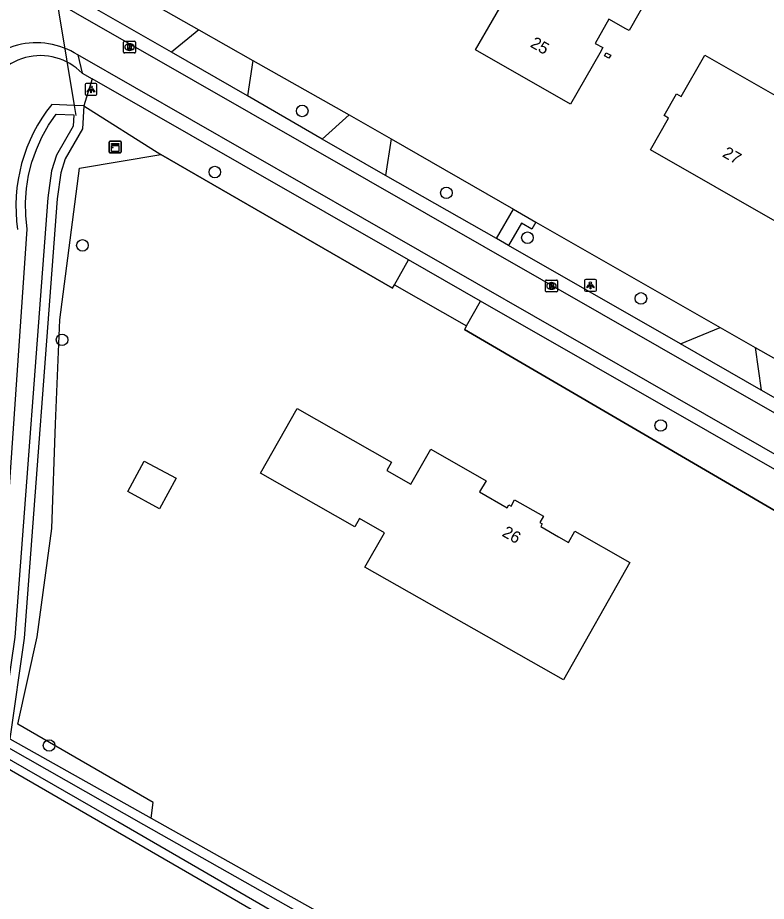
# Model space of a CAD drawing. Extents: x 156502 to 159074, y 384229 to 386094.
# Drawn here: x 157042.4 to 157105.6, y 385709.8 to 385784.4 of the extents above; entities that cross this region are included whole.
import ezdxf

# ---------------------------------------------------------------- set-up
doc = ezdxf.new("R2010")
doc.units = 0
for name, color, linetype in [('IMGEO_Berm_groen', 7, 'Continuous'), ('IMGEO_Berm_halfverhard', 7, 'Continuous'), ('IMGEO_Boom', 7, 'Continuous'), ('IMGEO_Duiker', 7, 'Continuous'), ('IMGEO_Erf', 7, 'Continuous'), ('IMGEO_Grasland_agrarisch', 7, 'Continuous'), ('IMGEO_Groenvoorziening', 7, 'Continuous'), ('IMGEO_Hek', 7, 'Continuous'), ('IMGEO_Kast', 7, 'Continuous'), ('IMGEO_Lichtpunt', 7, 'Continuous'), ('IMGEO_Muur', 7, 'Continuous'), ('IMGEO_Pand', 7, 'Continuous'), ('IMGEO_Pand_nummerreeks', 7, 'Continuous'), ('IMGEO_Rijbaan_lokaal_gesloten', 7, 'Continuous'), ('IMGEO_Rijbaan_lokaal_halfverhard', 7, 'Continuous'), ('IMGEO_Rijbaan_lokaal_open', 7, 'Continuous'), ('IMGEO_Rioolput', 7, 'Continuous'), ('IMGEO_Voetpad_open', 7, 'Continuous'), ('IMGEO_Waterloop', 7, 'Continuous')]:
    doc.layers.add(name, color=color, linetype=linetype)

msp = doc.modelspace()

# ---------------------------------------------------------------- linework, layer by layer
at = {"layer": 'IMGEO_Berm_groen'}
for points in [[(157062.278, 385780.824), (157070.393, 385776.216)], [(157073.942, 385774.201), (157084.266, 385768.252)], [(157086.152, 385767.162), (157101.744, 385758.276)], [(157104.7, 385756.591), (157109.515, 385753.847), (157111.678, 385752.607)]]:
    msp.add_lwpolyline(points, dxfattribs=at)
at = {"layer": 'IMGEO_Berm_halfverhard'}
msp.add_arc((157044.326, 385776.302), 4.923, 44.34925, 165.54113, dxfattribs=at)
at = {"layer": 'IMGEO_Boom'}
for centre in [(157066.435, 385776.556), (157059.057, 385771.395), (157078.606, 385769.643), (157085.455, 385765.849), (157047.874, 385765.203), (157095.045, 385760.722), (157046.154, 385757.226), (157096.713, 385749.995), (157045.059, 385722.974)]:
    msp.add_circle(centre, 0.489, dxfattribs=at)
at = {"layer": 'IMGEO_Duiker'}
msp.add_lwpolyline([(157047.357, 385776.176), (157047.216, 385777.024), (157043.935, 385796.78)], dxfattribs=at)
at = {"layer": 'IMGEO_Erf'}
msp.add_lwpolyline([(157053.67, 385716.85), (157130.083, 385674.016), (157162.143, 385703.286), (157165.17, 385704.25)], dxfattribs=at)
at = {"layer": 'IMGEO_Grasland_agrarisch'}
msp.add_lwpolyline([(157041.361, 385721.169), (157128.6, 385670.699)], dxfattribs=at)
at = {"layer": 'IMGEO_Groenvoorziening'}
for points in [[(157048.314, 385802.061), (157048.565, 385801.621), (157048.579, 385793.832), (157048.701, 385788.533), (157057.714, 385783.415)], [(157048.686, 385779.263), (157047.987, 385776.991)], [(157047.987, 385776.991), (157047.892, 385775.032), (157046.412, 385772.497), (157046.044, 385771.329), (157045.742, 385769.133), (157042.959, 385732.042), (157041.74, 385723.537)], [(157047.987, 385776.991), (157047.216, 385777.024), (157045.283, 385777.106)], [(157047.987, 385776.991), (157054.491, 385772.88)], [(157053.67, 385716.85), (157053.851, 385718.152), (157042.415, 385724.776), (157044.054, 385732.143), (157045.294, 385741.29), (157045.604, 385750.127), (157045.953, 385758.926), (157047.62, 385771.736), (157054.491, 385772.88)], [(157054.491, 385772.88), (157074.046, 385761.597), (157074.239, 385761.861)], [(157080.304, 385758.402), (157080.131, 385758.103), (157108.063, 385741.81), (157108.687, 385738.705)], [(157041.74, 385723.537), (157053.67, 385716.85)]]:
    msp.add_lwpolyline(points, dxfattribs=at)
msp.add_arc((157055.983, 385768.504), 13.729, 141.20338, 188.18721, dxfattribs=at)
at = {"layer": 'IMGEO_Hek'}
for points in [[(157048.314, 385802.061), (157048.565, 385801.621), (157048.579, 385793.832), (157048.701, 385788.533), (157057.714, 385783.415)], [(157057.714, 385783.415), (157062.278, 385780.824)], [(157062.278, 385780.824), (157070.393, 385776.216)], [(157070.393, 385776.216), (157073.942, 385774.201)], [(157073.942, 385774.201), (157084.266, 385768.252)], [(157074.046, 385761.597), (157054.491, 385772.88)], [(157084.266, 385768.252), (157086.152, 385767.162)], [(157086.152, 385767.162), (157101.744, 385758.276)], [(157108.687, 385738.705), (157108.063, 385741.81), (157080.131, 385758.103)], [(157101.744, 385758.276), (157104.7, 385756.591)], [(157104.7, 385756.591), (157109.515, 385753.847)]]:
    msp.add_lwpolyline(points, dxfattribs=at)
at = {"layer": 'IMGEO_Kast'}
for p, q in [((157050.14, 385773.083), (157050.14, 385773.924)), ((157050.14, 385773.924), (157050.14, 385773.083)), ((157050.215, 385774.008), (157051.056, 385774.008)), ((157051.056, 385774.008), (157050.215, 385774.008)), ((157051.14, 385773.933), (157051.14, 385773.092)), ((157051.14, 385773.092), (157051.14, 385773.933)), ((157051.065, 385773.008), (157050.224, 385773.008)), ((157050.224, 385773.008), (157051.065, 385773.008))]:
    msp.add_line(p, q, dxfattribs=at)
for points in [[(157050.335, 385773.798), (157050.935, 385773.798), (157050.935, 385773.713), (157050.335, 385773.713), (157050.335, 385773.798)], [(157050.335, 385773.623), (157050.935, 385773.623), (157050.935, 385773.134), (157050.335, 385773.134), (157050.335, 385773.623)]]:
    msp.add_lwpolyline(points, dxfattribs=at)
msp.add_circle((157050.419, 385773.472), 0.0377, dxfattribs=at)
for centre, start, end in [((157050.218, 385773.93), 92.4484, 184.28452), ((157050.218, 385773.93), 92.4484, 184.28452), ((157051.062, 385773.93), 2.4484, 94.28452), ((157051.062, 385773.93), 2.4484, 94.28452), ((157050.218, 385773.086), 182.4484, 274.28452), ((157050.218, 385773.086), 182.4484, 274.28452), ((157051.062, 385773.086), 272.4484, 4.28452), ((157051.062, 385773.086), 272.4484, 4.28452)]:
    msp.add_arc(centre, 0.0779, start, end, dxfattribs=at)
at = {"layer": 'IMGEO_Lichtpunt'}
for p, q in [((157049.001, 385778.874), (157048.193, 385778.874)), ((157049.001, 385778.874), (157048.193, 385778.874)), ((157048.099, 385778.779), (157048.099, 385777.972)), ((157048.099, 385778.779), (157048.099, 385777.972)), ((157049.095, 385777.972), (157049.095, 385778.779)), ((157049.095, 385777.972), (157049.095, 385778.779)), ((157048.193, 385777.878), (157049.001, 385777.878)), ((157048.193, 385777.878), (157049.001, 385777.878)), ((157090.279, 385762.234), (157090.279, 385761.427)), ((157090.279, 385762.234), (157090.279, 385761.427)), ((157091.181, 385762.329), (157090.373, 385762.329)), ((157091.181, 385762.329), (157090.373, 385762.329)), ((157091.275, 385761.427), (157091.275, 385762.234)), ((157091.275, 385761.427), (157091.275, 385762.234)), ((157090.373, 385761.333), (157091.181, 385761.333)), ((157090.373, 385761.333), (157091.181, 385761.333))]:
    msp.add_line(p, q, dxfattribs=at)
for points in [[(157048.473, 385778.443), (157048.512, 385778.415), (157048.324, 385778.153), (157048.286, 385778.18), (157048.473, 385778.443)], [(157048.575, 385778.395), (157048.622, 385778.395), (157048.622, 385778.073), (157048.575, 385778.073), (157048.575, 385778.395)], [(157048.685, 385778.415), (157048.723, 385778.442), (157048.91, 385778.18), (157048.871, 385778.152), (157048.685, 385778.415)], [(157090.653, 385761.898), (157090.692, 385761.87), (157090.504, 385761.608), (157090.466, 385761.635), (157090.653, 385761.898)], [(157090.755, 385761.85), (157090.802, 385761.85), (157090.802, 385761.528), (157090.755, 385761.528), (157090.755, 385761.85)], [(157090.865, 385761.87), (157090.903, 385761.897), (157091.09, 385761.635), (157091.051, 385761.607), (157090.865, 385761.87)]]:
    msp.add_lwpolyline(points, dxfattribs=at)
for centre in [(157048.598, 385778.577), (157090.778, 385762.032)]:
    msp.add_circle(centre, 0.0994, dxfattribs=at)
for centre, start, end in [((157048.193, 385778.779), 90, 180), ((157048.193, 385778.779), 90, 180), ((157049.001, 385778.779), 0, 90), ((157049.001, 385778.779), 0, 90), ((157048.193, 385777.972), 180, 270), ((157048.193, 385777.972), 180, 270), ((157049.001, 385777.972), 270, 0), ((157049.001, 385777.972), 270, 360), ((157090.373, 385762.234), 90, 180), ((157090.373, 385762.234), 90, 180), ((157091.181, 385762.234), 0, 90), ((157091.181, 385762.234), 0, 90), ((157090.373, 385761.427), 180, 270), ((157090.373, 385761.427), 180, 270), ((157091.181, 385761.427), 270, 0), ((157091.181, 385761.427), 270, 360)]:
    msp.add_arc(centre, 0.0946, start, end, dxfattribs=at)
at = {"layer": 'IMGEO_Muur'}
for points in [[(157091.968, 385781.202), (157092.112, 385781.467), (157092.485, 385781.264)], [(157092.341, 385780.999), (157091.968, 385781.202)], [(157092.485, 385781.264), (157092.341, 385780.999)]]:
    msp.add_lwpolyline(points, dxfattribs=at)
at = {"layer": 'IMGEO_Pand'}
for points in [[(157094.034, 385783.344), (157093.774, 385783.484), (157092.329, 385784.314), (157091.181, 385782.261), (157091.819, 385781.904), (157091.56, 385781.44), (157089.098, 385777.114), (157081.073, 385781.715), (157083.929, 385786.699), (157081.847, 385787.885), (157081.084, 385786.547), (157077.502, 385788.588), (157084.548, 385800.906), (157088.147, 385798.874), (157083.885, 385791.439), (157085.956, 385790.275), (157087.339, 385792.644), (157090.403, 385790.86), (157090.692, 385791.357), (157092.087, 385790.545), (157091.801, 385790.041), (157096.381, 385787.475), (157094.034, 385783.344)], [(157113.324, 385783.376), (157118.757, 385780.244), (157115.909, 385775.303), (157112.473, 385777.255), (157111.225, 385775.078), (157111.364, 385774.999), (157106.783, 385767.009), (157095.843, 385773.267), (157097.372, 385775.944), (157097.005, 385776.166), (157098.051, 385777.989), (157098.424, 385777.775), (157100.433, 385781.277), (157108.121, 385776.862), (157109.544, 385779.339), (157110.637, 385778.713), (157113.324, 385783.376)], [(157092.485, 385781.264), (157092.341, 385780.999), (157091.968, 385781.202), (157092.112, 385781.467), (157092.485, 385781.264)], [(157088.51, 385728.529), (157071.737, 385738.033), (157073.388, 385740.939), (157071.275, 385742.139), (157070.88, 385741.444), (157062.916, 385745.969), (157066.013, 385751.42), (157073.979, 385746.895), (157073.583, 385746.199), (157075.603, 385745.041), (157077.286, 385747.99), (157081.958, 385745.337), (157081.417, 385744.384), (157083.732, 385743.053), (157083.873, 385743.292), (157084.077, 385743.175), (157084.364, 385743.707), (157086.808, 385742.331), (157086.514, 385741.808), (157086.713, 385741.694), (157086.579, 385741.46), (157088.072, 385740.585), (157088.91, 385740.111), (157089.452, 385741.064), (157094.116, 385738.421), (157088.51, 385728.529)], [(157054.382, 385742.96), (157051.695, 385744.412), (157053.089, 385746.991), (157055.776, 385745.538), (157054.382, 385742.96)]]:
    msp.add_lwpolyline(points, dxfattribs=at)
at = {"layer": 'IMGEO_Rijbaan_lokaal_gesloten'}
for points in [[(157042.417, 385787.656), (157155.604, 385722.866)], [(157153.385, 385720.619), (157047.474, 385781.289)]]:
    msp.add_lwpolyline(points, dxfattribs=at)
msp.add_arc((157043.983, 385775.833), 6.477, 57.39126, 150.94914, dxfattribs=at)
at = {"layer": 'IMGEO_Rijbaan_lokaal_halfverhard'}
for points in [[(157055.407, 385781.512), (157048.506, 385785.444)], [(157047.474, 385781.289), (157047.846, 385779.743)], [(157047.846, 385779.743), (157048.686, 385779.263)], [(157075.399, 385763.984), (157061.322, 385772.036), (157048.686, 385779.263)], [(157068.127, 385774.18), (157061.801, 385777.83)], [(157082.83, 385765.787), (157073.474, 385771.108)], [(157083.861, 385765.187), (157082.83, 385765.787)], [(157098.368, 385756.889), (157083.861, 385765.187)], [(157110.277, 385744.036), (157081.499, 385760.496)], [(157110.239, 385750.099), (157105.201, 385752.99)]]:
    msp.add_lwpolyline(points, dxfattribs=at)
at = {"layer": 'IMGEO_Rijbaan_lokaal_open'}
for points in [[(157057.714, 385783.415), (157055.407, 385781.512)], [(157057.714, 385783.415), (157062.278, 385780.824)], [(157061.801, 385777.83), (157055.407, 385781.512)], [(157062.278, 385780.824), (157061.801, 385777.83)], [(157068.127, 385774.18), (157070.393, 385776.216)], [(157070.393, 385776.216), (157073.942, 385774.201)], [(157073.474, 385771.108), (157068.127, 385774.18)], [(157073.942, 385774.201), (157073.474, 385771.108)], [(157074.239, 385761.861), (157075.399, 385763.984)], [(157081.499, 385760.496), (157075.399, 385763.984)], [(157074.239, 385761.861), (157080.304, 385758.402)], [(157080.304, 385758.402), (157081.499, 385760.496)], [(157098.368, 385756.889), (157101.744, 385758.276)], [(157101.744, 385758.276), (157104.7, 385756.591)], [(157105.201, 385752.99), (157098.368, 385756.889)], [(157104.7, 385756.591), (157105.201, 385752.99)]]:
    msp.add_lwpolyline(points, dxfattribs=at)
at = {"layer": 'IMGEO_Rioolput'}
for p, q in [((157051.354, 385781.521), (157051.354, 385782.373)), ((157051.429, 385782.447), (157052.281, 385782.447)), ((157051.842, 385782.227), (157051.867, 385782.227)), ((157052.355, 385782.373), (157052.355, 385781.521)), ((157052.281, 385781.447), (157051.429, 385781.447)), ((157051.865, 385781.667), (157051.84, 385781.667)), ((157086.982, 385761.351), (157086.982, 385762.203)), ((157087.057, 385762.277), (157087.909, 385762.277)), ((157087.47, 385762.057), (157087.495, 385762.057)), ((157087.983, 385762.203), (157087.983, 385761.351)), ((157087.909, 385761.277), (157087.057, 385761.277)), ((157087.493, 385761.497), (157087.468, 385761.497))]:
    msp.add_line(p, q, dxfattribs=at)
for points in [[(157051.354, 385781.521), (157051.354, 385782.373)], [(157051.429, 385782.447), (157052.281, 385782.447)], [(157051.943, 385782.145), (157051.691, 385782.147), (157051.691, 385781.747)], [(157051.691, 385781.747), (157051.815, 385781.747), (157051.815, 385781.909), (157051.826, 385781.909)], [(157051.869, 385782.066), (157051.815, 385782.066), (157051.815, 385781.985)], [(157051.815, 385781.985), (157051.867, 385781.985)], [(157051.873, 385781.88), (157051.944, 385781.747), (157052.084, 385781.747), (157052.019, 385781.873)], [(157052.355, 385782.373), (157052.355, 385781.521)], [(157052.281, 385781.447), (157051.429, 385781.447)], [(157086.982, 385761.351), (157086.982, 385762.203)], [(157087.057, 385762.277), (157087.909, 385762.277)], [(157087.571, 385761.975), (157087.319, 385761.977), (157087.319, 385761.577)], [(157087.319, 385761.577), (157087.443, 385761.577), (157087.443, 385761.739), (157087.454, 385761.739)], [(157087.497, 385761.896), (157087.443, 385761.896), (157087.443, 385761.815)], [(157087.443, 385761.815), (157087.495, 385761.815)], [(157087.501, 385761.71), (157087.572, 385761.577), (157087.712, 385761.577), (157087.647, 385761.703)], [(157087.983, 385762.203), (157087.983, 385761.351)], [(157087.909, 385761.277), (157087.057, 385761.277)]]:
    msp.add_lwpolyline(points, dxfattribs=at)
for centre, radius, start, end in [((157051.431, 385782.371), 0.0765, 91.55205, 178.44795), ((157051.431, 385782.371), 0.0765, 91.55205, 178.44795), ((157051.825, 385781.856), 0.0533, 26.02933, 88.69889), ((157051.851, 385782.174), 0.19, 274.7715, 282.96867), ((157051.875, 385781.97), 0.0964, 77.00612, 93.18647), ((157051.889, 385782.027), 0.0378, 276.66336, 79.67722), ((157051.942, 385782.035), 0.109, 350.36119, 89.41601), ((157051.94, 385782.035), 0.112, 277.58423, 350.98172), ((157051.924, 385781.82), 0.108, 29.51342, 73.79051), ((157052.279, 385782.371), 0.0765, 1.55205, 88.44795), ((157052.279, 385782.371), 0.0765, 1.55205, 88.44795), ((157051.431, 385781.523), 0.0765, 181.55205, 268.44795), ((157051.431, 385781.523), 0.0765, 181.55205, 268.44795), ((157052.279, 385781.523), 0.0765, 271.55205, 358.44795), ((157052.279, 385781.523), 0.0765, 271.55205, 358.44795), ((157087.059, 385762.201), 0.0765, 91.55205, 178.44795), ((157087.059, 385762.201), 0.0765, 91.55205, 178.44795), ((157087.453, 385761.686), 0.0533, 26.02933, 88.69889), ((157087.479, 385762.004), 0.19, 274.7715, 282.96867), ((157087.503, 385761.8), 0.0964, 77.00612, 93.18647), ((157087.517, 385761.857), 0.0378, 276.66336, 79.67722), ((157087.57, 385761.865), 0.109, 350.36119, 89.41601), ((157087.568, 385761.865), 0.112, 277.58423, 350.98172), ((157087.552, 385761.65), 0.108, 29.51342, 73.79051), ((157087.907, 385762.201), 0.0765, 1.55205, 88.44795), ((157087.907, 385762.201), 0.0765, 1.55205, 88.44795), ((157087.059, 385761.353), 0.0765, 181.55205, 268.44795), ((157087.059, 385761.353), 0.0765, 181.55205, 268.44795), ((157087.907, 385761.353), 0.0765, 271.55205, 358.44795), ((157087.907, 385761.353), 0.0765, 271.55205, 358.44795)]:
    msp.add_arc(centre, radius, start, end, dxfattribs=at)
for centre, major_axis, ratio, start_param, end_param in [((157051.841, 385781.947), (-0.387, 0.002), 0.722429, 4.712389, 7.853982), ((157051.866, 385781.947), (-0.39, 0.002), 0.717154, 1.570796, 4.712389), ((157087.469, 385761.777), (-0.387, 0.002), 0.722429, 4.712389, 7.853982), ((157087.494, 385761.777), (-0.39, 0.002), 0.717154, 1.570796, 4.712389)]:
    msp.add_ellipse(centre, major_axis=major_axis, ratio=ratio, start_param=start_param, end_param=end_param, dxfattribs=at)
at = {"layer": 'IMGEO_Voetpad_open'}
for points in [[(157082.83, 385765.787), (157084.266, 385768.252)], [(157084.266, 385768.252), (157086.152, 385767.162)], [(157086.152, 385767.162), (157085.817, 385766.586), (157084.961, 385767.091), (157083.861, 385765.187)]]:
    msp.add_lwpolyline(points, dxfattribs=at)
at = {"layer": 'IMGEO_Waterloop'}
for points in [[(157042.159, 385732.129), (157041.097, 385724.718), (157039.74, 385725.344), (157040.811, 385732.089), (157043.202, 385766.58), (157043.082, 385767.716), (157043.063, 385768.858), (157043.145, 385769.997), (157043.326, 385771.124), (157043.607, 385772.231), (157043.984, 385773.309), (157044.455, 385774.349), (157045.016, 385775.344), (157045.663, 385776.285), (157047.145, 385776.222), (157047.098, 385775.267), (157045.672, 385772.825), (157045.257, 385771.506), (157044.942, 385769.218), (157042.159, 385732.129)], [(157041.24, 385723.767), (157041.2, 385723.209), (157041.602, 385722.806), (157053.036, 385716.305), (157079.167, 385701.542), (157100.636, 385688.921), (157128.657, 385673.175)], [(157128.318, 385672.451), (157100.715, 385687.7), (157076.092, 385701.913), (157050.852, 385716.529), (157040.926, 385722.25), (157040.55, 385722.131), (157040.422, 385721.651)]]:
    msp.add_lwpolyline(points, dxfattribs=at)

# ---------------------------------------------------------------- texts
at = {"layer": 'IMGEO_Pand_nummerreeks'}
for s, rotation, p in [('25', 330.17808, (157085.624, 385782.01)), ('27', 330.22817, (157101.849, 385772.734)), ('26', 330.59509, (157083.24, 385740.705))]:
    msp.add_text(s, height=1, rotation=rotation, dxfattribs=at).set_placement(p)

doc.saveas('drawing.dxf')
